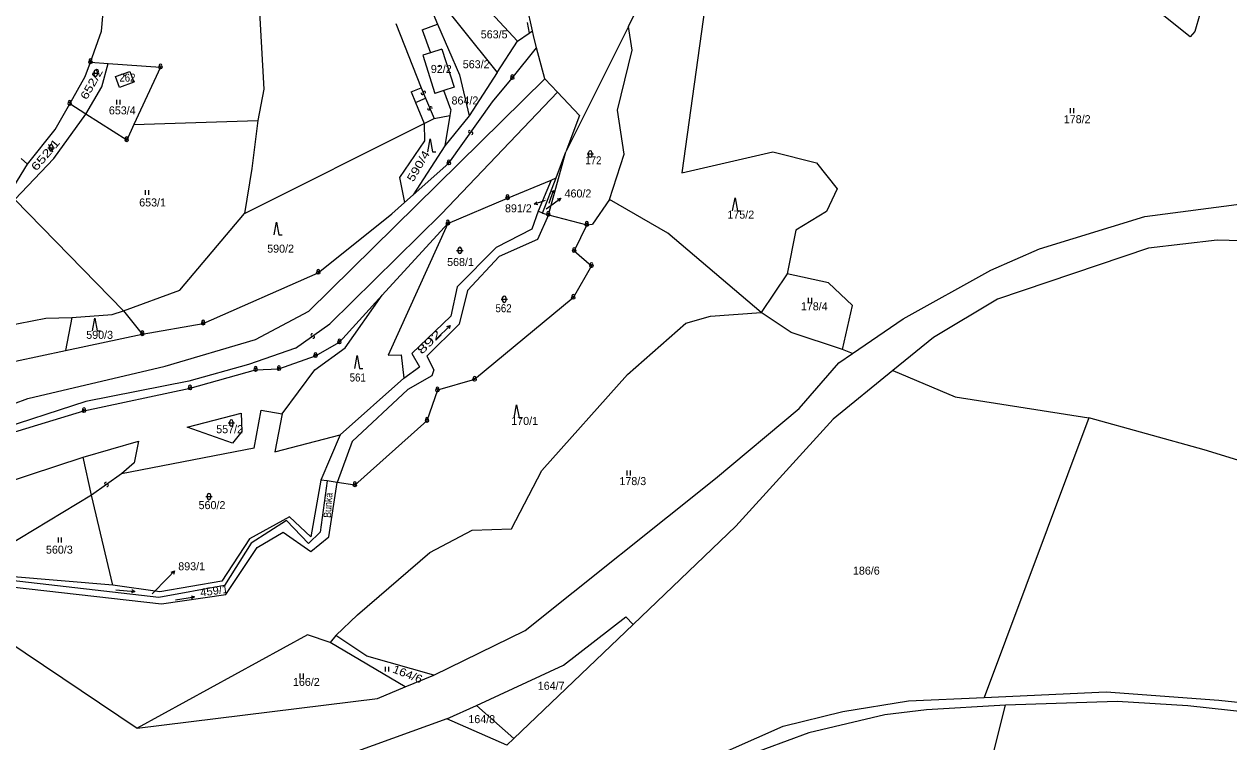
# Model space of a CAD drawing. Extents: x -680102 to -677253, y -1007548 to -1006096.
# Drawn here: x -679159.4 to -678783.2, y -1006966.4 to -1006742.4 of the extents above; entities that cross this region are included whole.
import ezdxf
from ezdxf.enums import TextEntityAlignment as Align

# ---------------------------------------------------------------- set-up
doc = ezdxf.new("R2010")
doc.units = 0
for name, color, linetype, lineweight in [('1', 7, 'Continuous', 25), ('13', 7, 'Continuous', 25), ('16', 7, 'Continuous', 25), ('24', 7, 'Continuous', 25), ('25', 7, 'Continuous', 25), ('4', 7, 'Continuous', 25)]:
    doc.layers.add(name, color=color, linetype=linetype, lineweight=lineweight)
for name, color, linetype in [('15', 7, 'Continuous'), ('18', 7, 'Continuous'), ('19', 7, 'Continuous')]:
    doc.layers.add(name, color=color, linetype=linetype)

msp = doc.modelspace()

# ---------------------------------------------------------------- linework, layer by layer
at = {"layer": '1'}
for p, q in [((-679135.24, -1006744.53), (-679133.78, -1006727.4)), ((-679005.39, -1006747.73), (-679016.43, -1006735.68)), ((-679043.31, -1006742.18), (-679035.43, -1006762.21)), ((-679035.14, -1006744.1), (-679030.31, -1006742.36)), ((-679002.29, -1006741.89), (-679001.73, -1006745.16)), ((-678970.65, -1006743.09), (-678990.21, -1006782.19)), ((-679035.14, -1006744.1), (-679032.54, -1006751.32)), ((-679028.96, -1006750.2), (-679025.16, -1006762.08)), ((-679011.73, -1006757.42), (-679005.39, -1006747.73)), ((-679034.94, -1006752.08), (-679031.17, -1006763.98)), ((-679135.12, -1006761.94), (-679133.12, -1006754.64)), ((-679023.46, -1006758.19), (-679020.47, -1006770.96)), ((-679011.73, -1006757.42), (-679020.47, -1006770.96)), ((-679140.14, -1006770.43), (-679135.12, -1006761.94)), ((-679038.52, -1006763.53), (-679035.43, -1006762.21)), ((-679038.52, -1006763.53), (-679037.16, -1006766.8)), ((-679026.19, -1006768.98), (-679028.33, -1006763.08)), ((-679037.16, -1006766.8), (-679034.45, -1006773.33)), ((-679026.19, -1006768.98), (-679026.42, -1006770.89)), ((-679150.14, -1006784.3), (-679140.14, -1006770.43)), ((-679125.14, -1006773.72), (-679086.42, -1006772.41)), ((-679086.42, -1006772.41), (-679088.34, -1006787.44)), ((-679031.41, -1006771.81), (-679026.42, -1006770.89)), ((-679026.42, -1006770.89), (-679028.05, -1006780.31)), ((-679158.38, -1006786.1), (-679160.3, -1006784.3)), ((-678995.7, -1006801.83), (-678990.21, -1006782.19)), ((-679088.34, -1006787.44), (-679090.55, -1006801.49)), ((-678994.87, -1006791.04), (-678998.87, -1006800.72)), ((-678976.56, -1006797.14), (-678981.88, -1006804.84)), ((-678809.39, -1006802.43), (-678778.41, -1006798.31)), ((-679110.83, -1006825.34), (-679090.55, -1006801.49)), ((-678998.87, -1006800.72), (-679000.9, -1006806.34)), ((-678995.7, -1006801.83), (-678999.08, -1006809.57)), ((-678997.48, -1006801.36), (-678998.87, -1006800.72)), ((-678842.31, -1006812.48), (-678809.39, -1006802.43)), ((-678983.68, -1006805), (-678981.88, -1006804.84)), ((-678929.27, -1006832.39), (-678958.38, -1006807.58)), ((-678921.1, -1006820.24), (-678929.27, -1006832.39)), ((-678908.17, -1006823.09), (-678921.1, -1006820.24)), ((-679059.14, -1006843.38), (-679047.56, -1006826.9)), ((-678945.03, -1006833.53), (-678929.27, -1006832.39)), ((-679144.52, -1006833.87), (-679146.48, -1006844.21)), ((-679068.6, -1006850.21), (-679059.14, -1006843.38)), ((-679038.31, -1006845.13), (-679035.91, -1006849.3)), ((-679078.87, -1006863.95), (-679068.6, -1006850.21)), ((-679040.83, -1006852.87), (-679035.91, -1006849.3)), ((-678888.1, -1006850.47), (-678868.7, -1006858.67)), ((-679060.69, -1006870.58), (-679040.83, -1006852.87)), ((-678868.7, -1006858.67), (-678826.88, -1006865.18)), ((-679087.61, -1006874.67), (-679085.35, -1006862.82)), ((-679085.35, -1006862.82), (-679078.87, -1006863.95)), ((-679078.87, -1006863.95), (-679081.13, -1006875.8)), ((-678826.88, -1006865.18), (-678859.62, -1006952.47)), ((-679081.13, -1006875.8), (-679060.69, -1006870.58)), ((-679060.69, -1006870.58), (-679066.74, -1006884.73)), ((-679087.61, -1006874.67), (-679129.02, -1006882.68)), ((-679123.69, -1006872.46), (-679125.1, -1006879.22)), ((-679138.35, -1006889.34), (-679141.01, -1006877.49)), ((-679125.1, -1006879.22), (-679129.02, -1006882.68)), ((-679064.79, -1006884.93), (-679066.74, -1006884.73)), ((-679138.35, -1006889.34), (-679165.22, -1006905.55)), ((-679131.72, -1006917.41), (-679138.35, -1006889.34)), ((-679040.38, -1006949.22), (-679063.81, -1006935.3)), ((-679006.47, -1006965.32), (-679018.19, -1006954.95))]:
    msp.add_line(p, q, dxfattribs=at)
for points in [[(-678798.75, -1006717.89), (-678794.19, -1006728.21), (-678792.25, -1006739.23), (-678793.8, -1006744.67), (-678795.23, -1006746.35), (-678804.55, -1006738.97), (-678825.66, -1006733.4), (-678849.98, -1006730.68)], [(-678972.03, -1006782.95), (-678974.11, -1006769.23), (-678969.55, -1006750.45), (-678970.65, -1006743.09), (-678964.92, -1006731.27), (-678952.59, -1006723.96), (-678944.63, -1006721.34)], [(-678944.63, -1006721.34), (-678954, -1006788.76), (-678925.55, -1006782.25), (-678911.96, -1006785.6), (-678905.55, -1006793.77), (-678908.87, -1006800.86), (-678918.43, -1006806.7), (-678921.1, -1006820.24)], [(-679020.07, -1006734.51), (-679034.41, -1006729.1), (-679011.73, -1006757.42)], [(-679086.25, -1006732.99), (-679084.6, -1006762.61), (-679086.42, -1006772.41)], [(-679032.56, -1006737.17), (-679030.31, -1006742.36), (-679023.46, -1006758.19)], [(-679145.19, -1006767.22), (-679140.31, -1006758.74), (-679138.7, -1006754.23), (-679135.24, -1006744.53)], [(-679005.39, -1006747.73), (-679001.73, -1006745.16), (-679000.69, -1006744.42)], [(-679028.96, -1006750.2), (-679032.54, -1006751.32), (-679034.94, -1006752.08)], [(-679138.7, -1006754.23), (-679133.12, -1006754.64), (-679116.84, -1006755.83)], [(-679116.84, -1006755.83), (-679125.14, -1006773.72), (-679127.38, -1006778.55)], [(-679025.16, -1006762.08), (-679028.33, -1006763.08), (-679031.17, -1006763.98)], [(-679158.38, -1006786.1), (-679149.77, -1006775.2), (-679145.19, -1006767.22)], [(-679127.38, -1006778.55), (-679140.14, -1006770.43), (-679145.19, -1006767.22)], [(-679090.55, -1006801.49), (-679034.45, -1006773.33), (-679031.41, -1006771.81)], [(-679020.47, -1006770.96), (-679028.05, -1006780.31), (-679037.88, -1006795.62)], [(-679034.45, -1006773.33), (-679034.4, -1006778.78), (-679042.21, -1006790.19), (-679040.59, -1006798.02)], [(-679213.53, -1006843.82), (-679197.32, -1006823.43), (-679177.95, -1006807.27), (-679162.34, -1006797.04), (-679150.14, -1006784.3)], [(-678958.38, -1006807.58), (-678976.56, -1006797.14), (-678972.03, -1006782.95)], [(-679213.53, -1006843.82), (-679199.98, -1006821.61), (-679180.43, -1006804.74), (-679162.59, -1006793.01), (-679158.38, -1006786.1)], [(-679008.45, -1006796.68), (-678994.87, -1006791.04), (-678993.3, -1006790.33)], [(-679044.62, -1006801.58), (-679040.59, -1006798.02), (-679037.88, -1006795.62)], [(-679162.34, -1006797.04), (-679128.41, -1006831.8), (-679122.51, -1006839.11)], [(-679107.61, -1006856.01), (-679087.12, -1006850.23), (-679079.84, -1006849.97), (-679068.42, -1006845.9), (-679060.96, -1006841.64), (-679047.56, -1006826.9), (-679027.08, -1006804.59), (-679008.45, -1006796.68)], [(-679122.51, -1006839.11), (-679103.5, -1006835.79), (-679067.57, -1006819.94), (-679044.62, -1006801.58)], [(-679027.08, -1006804.59), (-679045.75, -1006845.72), (-679041.68, -1006845.55), (-679040.83, -1006852.87)], [(-679000.9, -1006806.34), (-679011.96, -1006812.02), (-679024.22, -1006824.32), (-679026.2, -1006833.49), (-679038.31, -1006845.13)], [(-678999.08, -1006809.57), (-679011.1, -1006814.85), (-679020.97, -1006825.54), (-679023.52, -1006836.04), (-679033.68, -1006845.97), (-679031.44, -1006850.25), (-679032.05, -1006852.09), (-679039.59, -1006856.36), (-679056.99, -1006872.66), (-679061.7, -1006885.39)], [(-678757.2, -1006810.62), (-678786.87, -1006809.74), (-678808.33, -1006812.25), (-678855.42, -1006828.22), (-678875.46, -1006840.19)], [(-678884.85, -1006834.32), (-678857.52, -1006819.11), (-678842.31, -1006812.48)], [(-679131.87, -1006832.97), (-679128.41, -1006831.8), (-679110.83, -1006825.34)], [(-678903.88, -1006843.85), (-678900.68, -1006830.14), (-678908.17, -1006823.09)], [(-679152.68, -1006834.14), (-679144.52, -1006833.87), (-679131.87, -1006832.97)], [(-678900.68, -1006845.18), (-678903.88, -1006843.85), (-678919.9, -1006838.57), (-678929.27, -1006832.39)], [(-679213.53, -1006843.82), (-679199.32, -1006844.82), (-679174.12, -1006838.27), (-679152.68, -1006834.14)], [(-678971.03, -1006851.68), (-678952.81, -1006835.67), (-678945.03, -1006833.53)], [(-678904.95, -1006848.11), (-678900.68, -1006845.18), (-678884.85, -1006834.32)], [(-679162.14, -1006847.54), (-679146.48, -1006844.21), (-679122.51, -1006839.11)], [(-678875.46, -1006840.19), (-678888.1, -1006850.47), (-678906.79, -1006865.68)], [(-678943.48, -1006884.2), (-678917.35, -1006862.27), (-678904.95, -1006848.11)], [(-679062.06, -1006933.2), (-679055.26, -1006926.74), (-679032.73, -1006907.21), (-679019.52, -1006900.32), (-679007.18, -1006899.89), (-678997.7, -1006881.65), (-678971.03, -1006851.68)], [(-679173.35, -1006872.96), (-679140.72, -1006863.09), (-679107.61, -1006856.01)], [(-678906.79, -1006865.68), (-678937.15, -1006899.06), (-678969.23, -1006929.73)], [(-678619.34, -1006943.25), (-678679.89, -1006917.85), (-678712.96, -1006901.76), (-678742.78, -1006890), (-678790.92, -1006875.17), (-678826.88, -1006865.18)], [(-679183.16, -1006891.35), (-679141.01, -1006877.49), (-679123.69, -1006872.46)], [(-679188.77, -1006936.15), (-679176.67, -1006926.8), (-679163.36, -1006917.97), (-679116.48, -1006923.32), (-679096.46, -1006920.33), (-679086.65, -1006905.68), (-679078.57, -1006900.95), (-679069.87, -1006906.93), (-679064.27, -1006902.32), (-679061.7, -1006885.39)], [(-679066.74, -1006884.73), (-679069.85, -1006902.32), (-679076.57, -1006896.11), (-679088.99, -1006902.98), (-679097.64, -1006916.23), (-679117.02, -1006919.51)], [(-679031.43, -1006945.52), (-679002.93, -1006931.59), (-678943.48, -1006884.2)], [(-679117.02, -1006919.51), (-679131.72, -1006917.41), (-679163.98, -1006914.74)], [(-679176.67, -1006926.8), (-679124.12, -1006962.07), (-679049.04, -1006952.79)], [(-678990.99, -1006942.39), (-678971.48, -1006927.29), (-678969.23, -1006929.73)], [(-678969.23, -1006929.73), (-679006.47, -1006965.32), (-679008.63, -1006967.39)], [(-679063.81, -1006935.3), (-679070.87, -1006932.96), (-679124.12, -1006962.07)], [(-679031.43, -1006945.52), (-679052.34, -1006939.61), (-679062.06, -1006933.2), (-679063.81, -1006935.3)], [(-679027.42, -1006959.21), (-679018.19, -1006954.95), (-678990.99, -1006942.39)], [(-679049.04, -1006952.79), (-679040.38, -1006949.22), (-679031.43, -1006945.52)], [(-678954.38, -1006975.55), (-678922.39, -1006961.41), (-678903.77, -1006956.85), (-678883.21, -1006953.51)], [(-678883.21, -1006953.51), (-678859.62, -1006952.47), (-678821.5, -1006950.78)], [(-678741.11, -1006957.27), (-678763.59, -1006958.64), (-678796.05, -1006955.12), (-678818.04, -1006953.75), (-678852.96, -1006954.87)], [(-678821.5, -1006950.78), (-678786.36, -1006953.33), (-678764.64, -1006955.64)], [(-678870.13, -1007026.39), (-678866.73, -1007014.59), (-678861.38, -1006988.42), (-678852.96, -1006954.87), (-678877.65, -1006956.32), (-678890.58, -1006957.9), (-678914.35, -1006963.48), (-678934.64, -1006970.99), (-678950.61, -1006977.53), (-678960.58, -1006983.85)], [(-679008.63, -1006967.39), (-679027.42, -1006959.21), (-679061.3, -1006971.39)]]:
    msp.add_lwpolyline(points, dxfattribs=at)
for points in [[(-679130.9, -1006758.69), (-679126.37, -1006757.13), (-679125.18, -1006760.52), (-679129.66, -1006762.14)], [(-679108.47, -1006868.17), (-679091.64, -1006863.75), (-679091.47, -1006869.53), (-679094.36, -1006873.11)]]:
    msp.add_lwpolyline(points, close=True, dxfattribs=at)
at = {"layer": '13'}
for p, q in [((-678985.93, -1006770.9), (-678990.21, -1006782.19)), ((-679117.37, -1006921.28), (-679163.48, -1006916.03)), ((-679096.89, -1006917.53), (-679117.37, -1006921.28))]:
    msp.add_line(p, q, dxfattribs=at)
for points in [[(-679000.37, -1006745.89), (-679000.69, -1006744.42), (-679002.4, -1006736.58)], [(-678996.84, -1006759.45), (-678999.36, -1006749.75), (-679000.37, -1006745.89)], [(-678985.93, -1006770.9), (-678992.87, -1006763.62), (-678996.84, -1006759.45)], [(-678997.48, -1006801.36), (-678993.3, -1006790.33), (-678990.21, -1006782.19)], [(-678997.48, -1006801.36), (-678995.7, -1006801.83), (-678983.68, -1006805), (-678987.64, -1006813.16), (-678982.25, -1006817.83), (-678987.93, -1006827.73), (-679018.74, -1006853.31)], [(-679018.74, -1006853.31), (-679030.35, -1006856.61), (-679033.61, -1006866.15), (-679056.13, -1006886.22), (-679061.7, -1006885.39), (-679064.79, -1006884.93), (-679066.93, -1006900.88)], [(-679077.52, -1006897.24), (-679088.54, -1006904.3), (-679096.89, -1006917.53)], [(-679066.93, -1006900.88), (-679070.57, -1006904.41), (-679077.52, -1006897.24)]]:
    msp.add_lwpolyline(points, dxfattribs=at)
at = {"layer": '16'}
for p, q in [((-678997.25, -1006797.61), (-679000.086, -1006798.586)), ((-678996.68, -1006797.41), (-678997.25, -1006797.61)), ((-678996.36, -1006800.04), (-678994.24, -1006798.46)), ((-678994.24, -1006798.46), (-678991.835, -1006796.668)), ((-679119.4, -1006920.13), (-679114.57, -1006915.15)), ((-679114.57, -1006915.15), (-679112.475, -1006913.003))]:
    msp.add_line(p, q, dxfattribs=at)
for points in [[(-678998.978, -1006798.733), (-679000.086, -1006798.586), (-678999.303, -1006797.788)], [(-678992.936, -1006796.864), (-678991.835, -1006796.668), (-678992.338, -1006797.666)], [(-679113.532, -1006913.37), (-679112.475, -1006913.003), (-679112.816, -1006914.068)]]:
    msp.add_lwpolyline(points, dxfattribs=at)
at = {"layer": '24'}
for centre, radius in [((-679138.7, -1006754.23), 0.5), ((-679138.7, -1006754.23), 0.022), ((-679116.84, -1006755.83), 0.5), ((-679116.84, -1006755.83), 0.022), ((-679006.97, -1006759.19), 0.5), ((-679006.97, -1006759.19), 0.022), ((-679145.19, -1006767.22), 0.5), ((-679145.19, -1006767.22), 0.022), ((-679127.38, -1006778.55), 0.5), ((-679127.38, -1006778.55), 0.022), ((-679026.77, -1006785.78), 0.5), ((-679026.77, -1006785.78), 0.022), ((-679008.45, -1006796.68), 0.5), ((-679008.45, -1006796.68), 0.022), ((-678995.7, -1006801.83), 0.5), ((-678995.7, -1006801.83), 0.022), ((-679027.08, -1006804.59), 0.5), ((-679027.08, -1006804.59), 0.022), ((-678983.68, -1006805), 0.5), ((-678983.68, -1006805), 0.022), ((-678987.64, -1006813.16), 0.5), ((-678987.64, -1006813.16), 0.022), ((-678982.25, -1006817.83), 0.5), ((-678982.25, -1006817.83), 0.022), ((-679067.57, -1006819.94), 0.5), ((-679067.57, -1006819.94), 0.022), ((-678987.93, -1006827.73), 0.5), ((-678987.93, -1006827.73), 0.022), ((-679103.5, -1006835.79), 0.5), ((-679103.5, -1006835.79), 0.022), ((-679122.51, -1006839.11), 0.5), ((-679122.51, -1006839.11), 0.022), ((-679060.96, -1006841.64), 0.5), ((-679060.96, -1006841.64), 0.022), ((-679068.42, -1006845.9), 0.5), ((-679068.42, -1006845.9), 0.022), ((-679087.12, -1006850.23), 0.5), ((-679087.12, -1006850.23), 0.022), ((-679079.84, -1006849.97), 0.5), ((-679079.84, -1006849.97), 0.022), ((-679107.61, -1006856.01), 0.5), ((-679107.61, -1006856.01), 0.022), ((-679018.74, -1006853.31), 0.5), ((-679018.74, -1006853.31), 0.022), ((-679030.35, -1006856.61), 0.5), ((-679030.35, -1006856.61), 0.022), ((-679140.72, -1006863.09), 0.5), ((-679140.72, -1006863.09), 0.022), ((-679033.61, -1006866.15), 0.5), ((-679033.61, -1006866.15), 0.022), ((-679056.13, -1006886.22), 0.5), ((-679056.13, -1006886.22), 0.022)]:
    msp.add_circle(centre, radius, dxfattribs=at)
for centre in [(-679138.701, -1006753.667), (-679116.841, -1006755.267), (-679006.971, -1006758.627), (-679145.191, -1006766.657), (-679127.381, -1006777.987), (-679026.771, -1006785.217), (-679008.451, -1006796.117), (-678995.701, -1006801.267), (-679027.081, -1006804.027), (-678983.681, -1006804.437), (-678987.641, -1006812.597), (-678982.251, -1006817.267), (-679067.571, -1006819.377), (-678987.931, -1006827.167), (-679103.501, -1006835.227), (-679122.511, -1006838.547), (-679060.961, -1006841.077), (-679068.421, -1006845.337), (-679087.121, -1006849.667), (-679079.841, -1006849.407), (-679107.611, -1006855.447), (-679030.351, -1006856.047), (-679018.741, -1006852.747), (-679140.721, -1006862.527), (-679033.611, -1006865.587), (-679056.131, -1006885.657)]:
    msp.add_arc(centre, 0.437, 328.35109, 209.97456, dxfattribs=at)
at = {"layer": '25'}
for p, q in [((-679138.08, -1006757.69), (-679136.08, -1006757.69)), ((-679137.58, -1006758.19), (-679137.58, -1006757.19)), ((-679136.58, -1006757.19), (-679136.58, -1006758.19)), ((-679130.477, -1006767.455), (-679130.477, -1006765.955)), ((-679129.443, -1006767.455), (-679129.443, -1006765.955)), ((-678832.647, -1006770.105), (-678832.647, -1006768.605)), ((-678831.613, -1006770.105), (-678831.613, -1006768.605)), ((-679151.47, -1006781.47), (-679151.47, -1006780.47)), ((-679150.47, -1006780.47), (-679150.47, -1006781.47)), ((-679151.97, -1006780.97), (-679149.97, -1006780.97)), ((-678983.63, -1006782.88), (-678981.63, -1006782.88)), ((-678983.13, -1006783.38), (-678983.13, -1006782.38)), ((-678982.13, -1006782.38), (-678982.13, -1006783.38)), ((-679121.507, -1006795.635), (-679121.507, -1006794.135)), ((-679120.473, -1006795.635), (-679120.473, -1006794.135)), ((-678995.449, -1006798.26), (-678994.11, -1006794.279)), ((-679024.35, -1006812.98), (-679022.35, -1006812.98)), ((-679023.85, -1006813.48), (-679023.85, -1006812.48)), ((-679022.85, -1006812.48), (-679022.85, -1006813.48)), ((-679010.48, -1006828.21), (-679008.48, -1006828.21)), ((-679009.98, -1006828.71), (-679009.98, -1006827.71)), ((-679008.98, -1006827.71), (-679008.98, -1006828.71)), ((-678914.477, -1006829.315), (-678914.477, -1006827.815)), ((-678913.443, -1006829.315), (-678913.443, -1006827.815)), ((-679030.675, -1006840.546), (-679026.345, -1006836.394)), ((-679095.7, -1006866.83), (-679093.7, -1006866.83)), ((-679095.2, -1006867.33), (-679095.2, -1006866.33)), ((-679094.2, -1006866.33), (-679094.2, -1006867.33)), ((-678971.067, -1006883.195), (-678971.067, -1006881.695)), ((-678970.033, -1006883.195), (-678970.033, -1006881.695)), ((-679102.69, -1006889.8), (-679100.69, -1006889.8)), ((-679102.19, -1006890.3), (-679102.19, -1006889.3)), ((-679101.19, -1006889.3), (-679101.19, -1006890.3)), ((-679148.727, -1006904.115), (-679148.727, -1006902.615)), ((-679147.693, -1006904.115), (-679147.693, -1006902.615)), ((-679130.799, -1006918.935), (-679124.821, -1006919.425)), ((-679112.163, -1006921.994), (-679106.237, -1006921.066)), ((-679073.217, -1006946.545), (-679073.217, -1006945.045)), ((-679072.183, -1006946.545), (-679072.183, -1006945.045)), ((-679046.527, -1006944.385), (-679046.527, -1006942.885)), ((-679045.493, -1006944.385), (-679045.493, -1006942.885))]:
    msp.add_line(p, q, dxfattribs=at)
for points in [[(-679033.36, -1006782.19), (-679032.61, -1006778.19), (-679031.86, -1006782.19), (-679030.86, -1006782.19)], [(-678994.665, -1006794.831), (-678994.11, -1006794.279), (-678994.002, -1006795.054)], [(-678938.16, -1006800.6), (-678937.41, -1006796.6), (-678936.66, -1006800.6), (-678935.66, -1006800.6)], [(-679081.34, -1006808.16), (-679080.59, -1006804.16), (-679079.84, -1006808.16), (-679078.84, -1006808.16)], [(-679138.09, -1006838.09), (-679137.34, -1006834.09), (-679136.59, -1006838.09), (-679135.59, -1006838.09)], [(-679027.413, -1006836.725), (-679026.345, -1006836.394), (-679026.721, -1006837.447)], [(-679056.18, -1006849.82), (-679055.43, -1006845.82), (-679054.68, -1006849.82), (-679053.68, -1006849.82)], [(-679006.37, -1006865.19), (-679005.62, -1006861.19), (-679004.87, -1006865.19), (-679003.87, -1006865.19)], [(-679125.776, -1006918.846), (-679124.821, -1006919.425), (-679125.858, -1006919.842)], [(-679107.302, -1006920.727), (-679106.237, -1006921.066), (-679107.147, -1006921.714)]]:
    msp.add_lwpolyline(points, dxfattribs=at)
for centre in [(-679127.88, -1006758.38), (-679029.72, -1006755.46)]:
    msp.add_circle(centre, 0.175, dxfattribs=at)
for centre, radius, start, end in [((-679137.08, -1006757.19), 0.5, 0.101, 180.00143), ((-679137.08, -1006758.19), 0.5, 180.10243, 0.00286), ((-679035.092, -1006763.978), 0.369, 150.02474, 21.95827), ((-679034.41, -1006763.701), 0.367, 329.70443, 202.23751), ((-679033.072, -1006768.777), 0.368, 150.02474, 21.81375), ((-679032.39, -1006768.501), 0.367, 329.92459, 202.23751), ((-679020.249, -1006775.966), 0.368, 91.97062, 324.41056), ((-679019.651, -1006776.396), 0.369, 271.86478, 144.15937), ((-679150.97, -1006780.47), 0.5, 0.101, 180.00143), ((-679150.97, -1006781.47), 0.5, 180.10243, 0.00286), ((-678982.63, -1006782.38), 0.5, 0.101, 180.00143), ((-678982.63, -1006783.38), 0.5, 180.10243, 0.00286), ((-679023.35, -1006812.48), 0.5, 0.101, 180.00143), ((-679023.35, -1006813.48), 0.5, 180.10243, 0.00286), ((-679009.48, -1006827.71), 0.5, 0.101, 180.00143), ((-679009.48, -1006828.71), 0.5, 180.10243, 0.00286), ((-679069.509, -1006839.388), 0.368, 72.48695, 304.68771), ((-679069.091, -1006839.994), 0.368, 252.30473, 124.55342), ((-679094.7, -1006866.33), 0.5, 0.101, 180.00143), ((-679094.7, -1006867.33), 0.5, 180.10243, 0.00286), ((-679133.901, -1006885.707), 0.369, 72.64655, 304.57864), ((-679133.479, -1006886.311), 0.368, 252.70452, 125.03132), ((-679101.69, -1006889.3), 0.5, 0.101, 180.00143), ((-679101.69, -1006890.3), 0.5, 180.10243, 0.00286)]:
    msp.add_arc(centre, radius, start, end, dxfattribs=at)
at = {"layer": '4'}
for p, q in [((-679035.43, -1006762.21), (-679034.06, -1006765.47)), ((-679026.77, -1006785.78), (-679013.14, -1006766.57)), ((-679037.88, -1006795.62), (-679026.77, -1006785.78)), ((-679129.02, -1006882.68), (-679138.35, -1006889.34))]:
    msp.add_line(p, q, dxfattribs=at)
for points in [[(-679013.14, -1006766.57), (-679006.97, -1006759.19), (-678999.36, -1006749.75)], [(-679212.08, -1006879.19), (-679158.26, -1006859.18), (-679115.37, -1006849.13), (-679087.19, -1006840.79), (-679070.52, -1006831.96), (-678996.84, -1006759.45)], [(-679074.69, -1006843.49), (-679063.91, -1006835.88), (-679029.1, -1006801.55), (-678992.87, -1006763.62)], [(-679037.16, -1006766.8), (-679034.06, -1006765.47), (-679031.41, -1006771.81)], [(-679074.69, -1006843.49), (-679089.37, -1006848.62), (-679108, -1006853.77), (-679140.1, -1006860.15), (-679169.76, -1006869.71), (-679186.89, -1006877.28), (-679208.7, -1006885.37), (-679217.52, -1006890.28), (-679232.47, -1006900.58), (-679241.78, -1006908.92), (-679262.06, -1006923.28)]]:
    msp.add_lwpolyline(points, dxfattribs=at)

# ---------------------------------------------------------------- texts
at = {"layer": '15', "width": 0.9}
msp.add_text('Bunka', height=2.3, rotation=86.101, dxfattribs=at).set_placement((-679063.366, -1006892.585), align=Align.CENTER)
at = {"layer": '16'}
for s, p in [('460/2', (-678990.64, -1006796.46)), ('893/1', (-679111.28, -1006912.8))]:
    msp.add_text(s, height=2.5, dxfattribs=at).set_placement(p)
msp.add_text('891/2', height=2.5, dxfattribs=at).set_placement((-679000.88, -1006801.09), align=Align.RIGHT)
at = {"layer": '18'}
for s, height, p in [('563/5', 2.5, (-679016.82, -1006746.8)), ('563/2', 2.5, (-679022.43, -1006756.13)), ('864/2', 2.5, (-679025.94, -1006767.44)), ('653/4', 2.5, (-679132.95, -1006770.53)), ('178/2', 2.5, (-678834.74, -1006773.28)), ('653/1', 2.5, (-679123.48, -1006799.26)), ('460/2', 0.1, (-678996.16, -1006799.84)), ('175/2', 2.5, (-678939.79, -1006803.06)), ('590/2', 2.5, (-679083.51, -1006813.68)), ('568/1', 2.5, (-679027.32, -1006817.85)), ('178/4', 2.5, (-678916.84, -1006831.68)), ('590/3', 2.5, (-679140.02, -1006840.58)), ('170/1', 2.5, (-679007.29, -1006867.44)), ('557/2', 2.5, (-679099.43, -1006870.02)), ('178/3', 2.5, (-678973.51, -1006886.22)), ('186/6', 2.5, (-678900.58, -1006914.16)), ('166/2', 2.5, (-679075.47, -1006948.9)), ('164/7', 2.5, (-678999.01, -1006950.09)), ('164/8', 2.5, (-679020.68, -1006960.51))]:
    msp.add_text(s, height=height, dxfattribs=at).set_placement(p)
for s, height, rotation, width, p in [('652/2', 2.5, 60.3, 1.25, (-679139.864, -1006766.158)), ('652/1', 2.5, 49.8, 1.4, (-679155.593, -1006788.409)), ('590/4', 2.5, 59.7, 1.25, (-679037.891, -1006791.787)), ('891/2', 0.1, 67.501, 1.2, (-678996.788, -1006797.149)), ('459/1', 2.5, 8.1, 1.05, (-679104.251, -1006921.034)), ('164/6', 2.5, 338.603, 1.15, (-679044.571, -1006944.617))]:
    msp.add_text(s, height=height, rotation=rotation, dxfattribs=dict(at, width=width)).set_placement(p)
at = {"layer": '18', "width": 0.9}
msp.add_text('172', height=2.5, dxfattribs=at).set_placement((-678984.15, -1006786.11))
for s, p in [('562', (-679009.689, -1006832.27)), ('561', (-679055.23, -1006853.89))]:
    msp.add_text(s, height=2.5, dxfattribs=at).set_placement(p, align=Align.CENTER)
at = {"layer": '18', "width": 1.6}
msp.add_text('892', height=2.5, rotation=44.6, dxfattribs=at).set_placement((-679032.035, -1006842.454), align=Align.CENTER)
at = {"layer": '18'}
for s, height, p in [('560/2', 2.5, (-679100.75, -1006893.72)), ('560/3', 2.5, (-679148.41, -1006907.61)), ('893/1', 0.1, (-679119.199, -1006919.93))]:
    msp.add_text(s, height=height, dxfattribs=at).set_placement(p, align=Align.CENTER)
at = {"layer": '19', "width": 0.9}
msp.add_text('262', height=2.5, dxfattribs=at).set_placement((-679129.67, -1006760.31))
at = {"layer": '19'}
msp.add_text('92/2', height=2.5, dxfattribs=at).set_placement((-679032.4, -1006757.6))

doc.saveas('drawing.dxf')
